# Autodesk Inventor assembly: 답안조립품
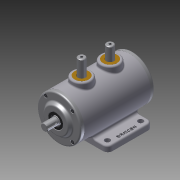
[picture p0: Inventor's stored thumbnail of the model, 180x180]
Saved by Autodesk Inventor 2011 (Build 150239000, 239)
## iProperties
Created: 2014-12
Part Number: 답안조립품
Document SubType Name: Assembly
Designer: user
Author: user
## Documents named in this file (10)
- D:\441225V1004\답안조립품.iam
- D:\441225V1004\1-본체.ipt
- D:\441225V1004\앞커버.ipt
- D:\441225V1004\베어링 6203.ipt
- D:\441225V1004\오일실.ipt
- D:\441225V1004\4-축.ipt
- D:\441225V1004\뒷커버.ipt
- D:\441225V1004\슬라이더.ipt
- D:\441225V1004\부시.ipt
- D:\441225V1004\M4-소켓머리.ipt
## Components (13 placed, 5 different names)
1. 1-본체:1
2. 7-베어링 6203:1
3. 8-오일실:1 — 플러쉬:1
4. 4-축:1 — 플러쉬:1
5. 7-베어링 6203:2
6. 9-M4-소켓머리:1
7. 9-M4-소켓머리:2
8. 9-M4-소켓머리:3
9. 9-M4-소켓머리:4
10. 9-M4-소켓머리:5
11. 9-M4-소켓머리:6
12. 9-M4-소켓머리:7
13. 9-M4-소켓머리:8
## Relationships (1: Flush 1)
- 플러쉬:1 [Flush]: 8-오일실:1 ↔ 4-축:1
